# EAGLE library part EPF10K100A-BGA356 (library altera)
EPF10K100 FLEX 10K family
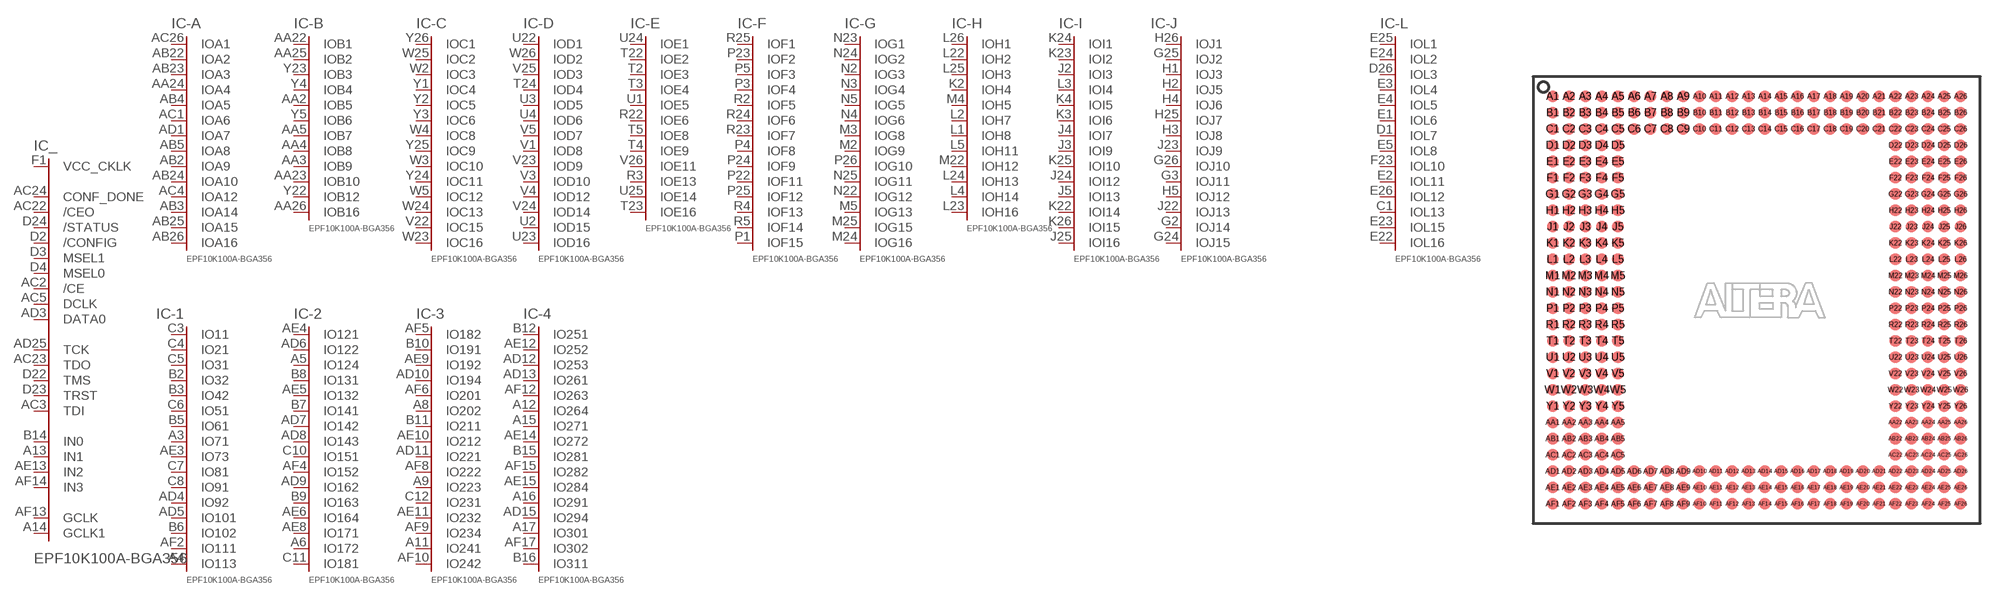
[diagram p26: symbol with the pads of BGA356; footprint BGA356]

Designator prefix IC; gates _=100B356C -A=100A16 -B=100B16 -C=100C16 -D=100D16 -E=100E16 -F=100F15 -G=100G16 -H=100H16 -I=100I16 -J=100J15 -L=100L16 -1=100-113 -2=100-181 -3=100-242 -4=100-311 -5=100-402 -6=100-473 -7=100-524 -K=100K15 G1=GNDINT G2=GNDINT G3=GNDINT G4=GNDINT G5=GNDINT G6=GNDINT G7=GNDINT G8=GNDINT G9=GNDINT G10=GNDINT G11=GNDINT G12=GNDINT G13=GNDINT G14=GNDINT G15=GNDINT G16=GNDINT G17=GNDINT G18=GNDINT G19=GNDINT G20=GNDINT G21=GNDINT G22=GNDINT G23=GNDINT G24=GNDINT G25=GNDINT G26=GNDINT G27=GNDINT G28=GNDINT G29=GNDINT G30=GNDINT G31=GNDINT G32=GNDINT G33=GNDINT V1=VCCINT V2=VCCINT V3=VCCINT V4=VCCINT V5=VCCINT V6=VCCINT V7=VCCINT V8=VCCINT V9=VCCINT V10=VCCINT V11=VCCINT V12=VCCINT V13=VCCINT V14=VCCINT V15=VCCINT VO1=VCCIO VO2=VCCIO VO3=VCCIO VO4=VCCIO VO5=VCCIO VO6=VCCIO VO7=VCCIO VO8=VCCIO VO9=VCCIO VO10=VCCIO VO11=VCCIO VO12=VCCIO VO13=VCCIO VO14=VCCIO VO15=VCCIO VO16=VCCIO VO17=VCCIO VO18=VCCIO VO19=VCCIO

## EPF10K100A-BGA356 (MPN: EPF10K100ABC356-1; OC_FARNELL: unknown; OC_NEWARK: 51R8777)  [BGA356]
A1  V5:VCC  pwr
A2  G12:GND  pwr
A3  -1:IO71
A4  -1:IO113
A5  -2:IO124
A6  -2:IO172
A7  VO7:VCCIO  pwr
A8  -3:IO202
A9  -3:IO223
A10  G13:GND  pwr
A11  -3:IO241
A12  -4:IO264
A13  _:IN1  in
A14  _:GCLK1  in
A15  -4:IO271
A16  -4:IO291
A17  -4:IO301
A18  -5:IO321
A19  -5:IO351
A20  G14:GND  pwr
A21  -5:IO402
A22  -5:IO401
A23  VO8:VCCIO  pwr
A24  -6:IO421
A25  -6:IO451
A26  V6:VCC  pwr
AA1  V1:VCC  pwr
AA2  -B:IOB5
AA3  -B:IOB9
AA4  -B:IOB8
AA5  -B:IOB7
AA22  -B:IOB1
AA23  -B:IOB10
AA24  -A:IOA4
AA25  -B:IOB2
AA26  -B:IOB16
AB1  VO1:VCCIO  pwr
AB2  -A:IOA9
AB3  -A:IOA14
AB4  -A:IOA5
AB5  -A:IOA8
AB22  -A:IOA2
AB23  -A:IOA3
AB24  -A:IOA10
AB25  -A:IOA15
AB26  -A:IOA16
AC1  -A:IOA6
AC2  _:/CE  in
AC3  _:TDI
AC4  -A:IOA12
AC5  _:DCLK  in
AC22  _:/CEO  in
AC23  _:TDO
AC24  _:CONF_DONE  in
AC25  VO2:VCCIO  pwr
AC26  -A:IOA1
AD1  -A:IOA7
AD2  G1:GND  pwr
AD3  _:DATA0  in
AD4  -1:IO92
AD5  -1:IO101
AD6  -2:IO122
AD7  -2:IO142
AD8  -2:IO143
AD9  -2:IO162
AD10  -3:IO194
AD11  -3:IO221
AD12  -4:IO253
AD13  -4:IO261
AD14  G2:GND  pwr
AD15  -4:IO294
AD16  -5:IO364
AD17  -5:IO391
AD18  VO3:VCCIO  pwr
AD19  -6:IO461
AD20  G3:GND  pwr
AD21  -7:IO501
AD22  -7:IO524
AD23  -7:IO512
AD24  -7:IO522
AD25  _:TCK
AD26  V2:VCC  pwr
AE1  G4:GND  pwr
AE2  G5:GND  pwr
AE3  -1:IO73
AE4  -2:IO121
AE5  -2:IO132
AE6  -2:IO164
AE7  G6:GND  pwr
AE8  -2:IO171
AE9  -3:IO192
AE10  -3:IO212
AE11  -3:IO232
AE12  -4:IO252
AE13  _:IN2  in
AE14  -4:IO272
AE15  -4:IO284
AE16  -5:IO323
AE17  -5:IO353
AE18  -5:IO381
AE19  -6:IO423
AE20  -6:IO441
AE21  -6:IO452
AE22  -7:IO482
AE23  -7:IO491
AE24  -7:IO502
AE25  G7:GND  pwr
AE26  G8:GND  pwr
AF1  V3:VCC  pwr
AF2  -1:IO111
AF3  VO4:VCCIO  pwr
AF4  -2:IO152
AF5  -3:IO182
AF6  -3:IO201
AF7  VO5:VCCIO  pwr
AF8  -3:IO222
AF9  -3:IO234
AF10  -3:IO242
AF11  G9:GND  pwr
AF12  -4:IO263
AF13  _:GCLK  in
AF14  _:IN3  in
AF15  -4:IO282
AF16  VO6:VCCIO  pwr
AF17  -4:IO302
AF18  -5:IO333
AF19  G10:GND  pwr
AF20  -5:IO371
AF21  -6:IO404
AF22  -6:IO411
AF23  -6:IO432
AF24  -6:IO471
AF25  G11:GND  pwr
AF26  V4:VCC  pwr
B1  G15:GND  pwr
B2  -1:IO32
B3  -1:IO42
B4  VO9:VCCIO  pwr
B5  -1:IO61
B6  -1:IO102
B7  -2:IO141
B8  -2:IO131
B9  -2:IO163
B10  -3:IO191
B11  -3:IO211
B12  -4:IO251
B13  G16:GND  pwr
B14  _:IN0  in
B15  -4:IO281
B16  -4:IO311
B17  -5:IO331
B18  -5:IO372
B19  -6:IO413
B20  -6:IO414
B21  -6:IO443
B22  G17:GND  pwr
B23  -6:IO473
B24  -7:IO492
B25  G18:GND  pwr
B26  G19:GND  pwr
C1  -L:IOL13
C2  G20:GND  pwr
C3  -1:IO11
C4  -1:IO21
C5  -1:IO31
C6  -1:IO51
C7  -1:IO81
C8  -1:IO91
C9  G21:GND  pwr
C10  -2:IO151
C11  -2:IO181
C12  -3:IO231
C13  G22:GND  pwr
C14  V7:VCC  pwr
C15  VO10:VCCIO  pwr
C16  -5:IO341
C17  -5:IO392
C18  -5:IO361
C19  -6:IO431
C20  -6:IO462
C21  -7:IO481
C22  -7:IO511
C23  -7:IO504
C24  -7:IO521
C25  G23:GND  pwr
C26  V8:VCC  pwr
D1  -L:IOL7
D2  _:/CONFIG  in
D3  _:MSEL1  in
D4  _:MSEL0  in
D5  V9:VCC  pwr
D22  _:TMS
D23  _:TRST
D24  _:/STATUS  in
D25  VO11:VCCIO  pwr
D26  -L:IOL3
E1  -L:IOL6
E2  -L:IOL11
E3  -L:IOL4
E4  -L:IOL5
E5  -L:IOL8
E22  -L:IOL16
E23  -L:IOL15
E24  -L:IOL2
E25  -L:IOL1
E26  -L:IOL12
F1  _:VCC_CKLK  pas
F2  -K:IOK3
F3  -K:IOK8
F4  VO12:VCCIO  pwr
F5  -K:IOK14
F22  -K:IOK2
F23  -L:IOL10
F24  -K:IOK15
F25  -K:IOK1
F26  -K:IOK7
G1  -K:IOK10
G2  -J:IOJ14
G3  -J:IOJ11
G4  -K:IOK4
G5  -K:IOK5
G22  -K:IOK11
G23  -K:IOK6
G24  -J:IOJ15
G25  -J:IOJ2
G26  -J:IOJ10
H1  -J:IOJ3
H2  -J:IOJ5
H3  -J:IOJ8
H4  -J:IOJ6
H5  -J:IOJ12
H22  V10:VCC  pwr
H23  G24:GND  pwr
H24  VO13:VCCIO  pwr
H25  -J:IOJ7
H26  -J:IOJ1
J1  V11:VCC  pwr
J2  -I:IOI3
J3  -I:IOI9
J4  -I:IOI7
J5  -I:IOI13
J22  -J:IOJ13
J23  -J:IOJ9
J24  -I:IOI12
J25  -I:IOI16
J26  G25:GND  pwr
K1  G26:GND  pwr
K2  -H:IOH4
K3  -I:IOI6
K4  -I:IOI5
K5  VO14:VCCIO  pwr
K22  -I:IOI14
K23  -I:IOI2
K24  -I:IOI1
K25  -I:IOI10
K26  -I:IOI15
L1  -H:IOH8
L2  -H:IOH7
L3  -I:IOI4
L4  -H:IOH14
L5  -H:IOH11
L22  -H:IOH2
L23  -H:IOH16
L24  -H:IOH13
L25  -H:IOH3
L26  -H:IOH1
M1  G27:GND  pwr
M2  -G:IOG9
M3  -G:IOG8
M4  -H:IOH5
M5  -G:IOG13
M22  -H:IOH12
M23  VO15:VCCIO  pwr
M24  -G:IOG16
M25  -G:IOG15
M26  V12:VCC  pwr
N1  V13:VCC  pwr
N2  -G:IOG3
N3  -G:IOG4
N4  -G:IOG6
N5  -G:IOG5
N22  -G:IOG12
N23  -G:IOG1
N24  -G:IOG2
N25  -G:IOG11
N26  G28:GND  pwr
P1  -F:IOF15
P2  VO16:VCCIO  pwr
P3  -F:IOF4
P4  -F:IOF8
P5  -F:IOF3
P22  -F:IOF11
P23  -F:IOF2
P24  -F:IOF9
P25  -F:IOF12
P26  -G:IOG10
R1  G29:GND  pwr
R2  -F:IOF5
R3  -E:IOE13
R4  -F:IOF13
R5  -F:IOF14
R22  -E:IOE6
R23  -F:IOF7
R24  -F:IOF6
R25  -F:IOF1
R26  G30:GND  pwr
T1  G31:GND  pwr
T2  -E:IOE3
T3  -E:IOE4
T4  -E:IOE9
T5  -E:IOE8
T22  -E:IOE2
T23  -E:IOE16
T24  -D:IOD4
T25  VO17:VCCIO  pwr
T26  V14:VCC  pwr
U1  -E:IOE5
U2  -D:IOD15
U3  -D:IOD5
U4  -D:IOD6
U5  V15:VCC  pwr
U22  -D:IOD1
U23  -D:IOD16
U24  -E:IOE1
U25  -E:IOE14
U26  G32:GND  pwr
V1  -D:IOD8
V2  VO18:VCCIO  pwr
V3  -D:IOD10
V4  -D:IOD12
V5  -D:IOD7
V22  -C:IOC15
V23  -D:IOD9
V24  -D:IOD14
V25  -D:IOD3
V26  -E:IOE11
W1  G33:GND  pwr
W2  -C:IOC3
W3  -C:IOC10
W4  -C:IOC8
W5  -C:IOC12
W22  VO19:VCCIO  pwr
W23  -C:IOC16
W24  -C:IOC13
W25  -C:IOC2
W26  -D:IOD2
Y1  -C:IOC4
Y2  -C:IOC5
Y3  -C:IOC6
Y4  -B:IOB4
Y5  -B:IOB6
Y22  -B:IOB12
Y23  -B:IOB3
Y24  -C:IOC11
Y25  -C:IOC9
Y26  -C:IOC1

## Footprint BGA356 (pad centres in mm)
Ball Grid Array
smd 0.9 x 0.9: A1 -15.875,15.875; A2 -14.605,15.875; A3 -13.335,15.875; A4 -12.065,15.875; A5 -10.795,15.875; A6 -9.525,15.875; A7 -8.255,15.875; A8 -6.985,15.875; A9 -5.715,15.875; A10 -4.445,15.875; A11 -3.175,15.875; A12 -1.905,15.875; A13 -0.635,15.875; A14 0.635,15.875; A15 1.905,15.875; A16 3.175,15.875; A17 4.445,15.875; A18 5.715,15.875; A19 6.985,15.875; A20 8.255,15.875; A21 9.525,15.875; A22 10.795,15.875; A23 12.065,15.875; A24 13.335,15.875; A25 14.605,15.875; A26 15.875,15.875; AA1 -15.875,-9.525; AA2 -14.605,-9.525; AA3 -13.335,-9.525; AA4 -12.065,-9.525; AA5 -10.795,-9.525; AA22 10.795,-9.525; AA23 12.065,-9.525; AA24 13.335,-9.525; AA25 14.605,-9.525; AA26 15.875,-9.525; AB1 -15.875,-10.795; AB2 -14.605,-10.795; AB3 -13.335,-10.795; AB4 -12.065,-10.795; AB5 -10.795,-10.795; AB22 10.795,-10.795; AB23 12.065,-10.795; AB24 13.335,-10.795; AB25 14.605,-10.795; AB26 15.875,-10.795; AC1 -15.875,-12.065; AC2 -14.605,-12.065; AC3 -13.335,-12.065; AC4 -12.065,-12.065; AC5 -10.795,-12.065; AC22 10.795,-12.065; AC23 12.065,-12.065; AC24 13.335,-12.065; AC25 14.605,-12.065; AC26 15.875,-12.065; AD1 -15.875,-13.335; AD2 -14.605,-13.335; AD3 -13.335,-13.335; AD4 -12.065,-13.335; AD5 -10.795,-13.335; AD6 -9.525,-13.335; AD7 -8.255,-13.335; AD8 -6.985,-13.335; AD9 -5.715,-13.335; AD10 -4.445,-13.335; AD11 -3.175,-13.335; AD12 -1.905,-13.335; AD13 -0.635,-13.335; AD14 0.635,-13.335; AD15 1.905,-13.335; AD16 3.175,-13.335; AD17 4.445,-13.335; AD18 5.715,-13.335; AD19 6.985,-13.335; AD20 8.255,-13.335; AD21 9.525,-13.335; AD22 10.795,-13.335; AD23 12.065,-13.335; AD24 13.335,-13.335; AD25 14.605,-13.335; AD26 15.875,-13.335; AE1 -15.875,-14.605; AE2 -14.605,-14.605; AE3 -13.335,-14.605; AE4 -12.065,-14.605; AE5 -10.795,-14.605; AE6 -9.525,-14.605; AE7 -8.255,-14.605; AE8 -6.985,-14.605; AE9 -5.715,-14.605; AE10 -4.445,-14.605; AE11 -3.175,-14.605; AE12 -1.905,-14.605; AE13 -0.635,-14.605; AE14 0.635,-14.605; AE15 1.905,-14.605; AE16 3.175,-14.605; AE17 4.445,-14.605; AE18 5.715,-14.605; AE19 6.985,-14.605; AE20 8.255,-14.605; AE21 9.525,-14.605; AE22 10.795,-14.605; AE23 12.065,-14.605; AE24 13.335,-14.605; AE25 14.605,-14.605; AE26 15.875,-14.605; AF1 -15.875,-15.875; AF2 -14.605,-15.875; AF3 -13.335,-15.875; AF4 -12.065,-15.875; AF5 -10.795,-15.875; AF6 -9.525,-15.875; AF7 -8.255,-15.875; AF8 -6.985,-15.875; AF9 -5.715,-15.875; AF10 -4.445,-15.875; AF11 -3.175,-15.875; AF12 -1.905,-15.875; AF13 -0.635,-15.875; AF14 0.635,-15.875; AF15 1.905,-15.875; AF16 3.175,-15.875; AF17 4.445,-15.875; AF18 5.715,-15.875; AF19 6.985,-15.875; AF20 8.255,-15.875; AF21 9.525,-15.875; AF22 10.795,-15.875; AF23 12.065,-15.875; AF24 13.335,-15.875; AF25 14.605,-15.875; AF26 15.875,-15.875; B1 -15.875,14.605; B2 -14.605,14.605; B3 -13.335,14.605; B4 -12.065,14.605; B5 -10.795,14.605; B6 -9.525,14.605; B7 -8.255,14.605; B8 -6.985,14.605; B9 -5.715,14.605; B10 -4.445,14.605; B11 -3.175,14.605; B12 -1.905,14.605; B13 -0.635,14.605; B14 0.635,14.605; B15 1.905,14.605; B16 3.175,14.605; B17 4.445,14.605; B18 5.715,14.605; B19 6.985,14.605; B20 8.255,14.605; B21 9.525,14.605; B22 10.795,14.605; B23 12.065,14.605; B24 13.335,14.605; B25 14.605,14.605; B26 15.875,14.605; C1 -15.875,13.335; C2 -14.605,13.335; C3 -13.335,13.335; C4 -12.065,13.335; C5 -10.795,13.335; C6 -9.525,13.335; C7 -8.255,13.335; C8 -6.985,13.335; C9 -5.715,13.335; C10 -4.445,13.335; C11 -3.175,13.335; C12 -1.905,13.335; C13 -0.635,13.335; C14 0.635,13.335; C15 1.905,13.335; C16 3.175,13.335; C17 4.445,13.335; C18 5.715,13.335; C19 6.985,13.335; C20 8.255,13.335; C21 9.525,13.335; C22 10.795,13.335; C23 12.065,13.335; C24 13.335,13.335; C25 14.605,13.335; C26 15.875,13.335; D1 -15.875,12.065; D2 -14.605,12.065; D3 -13.335,12.065; D4 -12.065,12.065; D5 -10.795,12.065; D22 10.795,12.065; D23 12.065,12.065; D24 13.335,12.065; D25 14.605,12.065; D26 15.875,12.065; E1 -15.875,10.795; E2 -14.605,10.795; E3 -13.335,10.795; E4 -12.065,10.795; E5 -10.795,10.795; E22 10.795,10.795; E23 12.065,10.795; E24 13.335,10.795; E25 14.605,10.795; E26 15.875,10.795; F1 -15.875,9.525; F2 -14.605,9.525; F3 -13.335,9.525; F4 -12.065,9.525; F5 -10.795,9.525; F22 10.795,9.525; F23 12.065,9.525; F24 13.335,9.525; F25 14.605,9.525; F26 15.875,9.525; G1 -15.875,8.255; G2 -14.605,8.255; G3 -13.335,8.255; G4 -12.065,8.255; G5 -10.795,8.255; G22 10.795,8.255; G23 12.065,8.255; G24 13.335,8.255; G25 14.605,8.255; G26 15.875,8.255; H1 -15.875,6.985; H2 -14.605,6.985; H3 -13.335,6.985; H4 -12.065,6.985; H5 -10.795,6.985; H22 10.795,6.985; H23 12.065,6.985; H24 13.335,6.985; H25 14.605,6.985; H26 15.875,6.985; J1 -15.875,5.715; J2 -14.605,5.715; J3 -13.335,5.715; J4 -12.065,5.715; J5 -10.795,5.715; J22 10.795,5.715; J23 12.065,5.715; J24 13.335,5.715; J25 14.605,5.715; J26 15.875,5.715; K1 -15.875,4.445; K2 -14.605,4.445; K3 -13.335,4.445; K4 -12.065,4.445; K5 -10.795,4.445; K22 10.795,4.445; K23 12.065,4.445; K24 13.335,4.445; K25 14.605,4.445; K26 15.875,4.445; L1 -15.875,3.175; L2 -14.605,3.175; L3 -13.335,3.175; L4 -12.065,3.175; L5 -10.795,3.175; L22 10.795,3.175; L23 12.065,3.175; L24 13.335,3.175; L25 14.605,3.175; L26 15.875,3.175; M1 -15.875,1.905; M2 -14.605,1.905; M3 -13.335,1.905; M4 -12.065,1.905; M5 -10.795,1.905; M22 10.795,1.905; M23 12.065,1.905; M24 13.335,1.905; M25 14.605,1.905; M26 15.875,1.905; N1 -15.875,0.635; N2 -14.605,0.635; N3 -13.335,0.635; N4 -12.065,0.635; N5 -10.795,0.635; N22 10.795,0.635; N23 12.065,0.635; N24 13.335,0.635; N25 14.605,0.635; N26 15.875,0.635; P1 -15.875,-0.635; P2 -14.605,-0.635; P3 -13.335,-0.635; P4 -12.065,-0.635; P5 -10.795,-0.635; P22 10.795,-0.635; P23 12.065,-0.635; P24 13.335,-0.635; P25 14.605,-0.635; P26 15.875,-0.635; R1 -15.875,-1.905; R2 -14.605,-1.905; R3 -13.335,-1.905; R4 -12.065,-1.905; R5 -10.795,-1.905; R22 10.795,-1.905; R23 12.065,-1.905; R24 13.335,-1.905; R25 14.605,-1.905; R26 15.875,-1.905; T1 -15.875,-3.175; T2 -14.605,-3.175; T3 -13.335,-3.175; T4 -12.065,-3.175; T5 -10.795,-3.175; T22 10.795,-3.175; T23 12.065,-3.175; T24 13.335,-3.175; T25 14.605,-3.175; T26 15.875,-3.175; U1 -15.875,-4.445; U2 -14.605,-4.445; U3 -13.335,-4.445; U4 -12.065,-4.445; U5 -10.795,-4.445; U22 10.795,-4.445; U23 12.065,-4.445; U24 13.335,-4.445; U25 14.605,-4.445; U26 15.875,-4.445; V1 -15.875,-5.715; V2 -14.605,-5.715; V3 -13.335,-5.715; V4 -12.065,-5.715; V5 -10.795,-5.715; V22 10.795,-5.715; V23 12.065,-5.715; V24 13.335,-5.715; V25 14.605,-5.715; V26 15.875,-5.715; W1 -15.875,-6.985; W2 -14.605,-6.985; W3 -13.335,-6.985; W4 -12.065,-6.985; W5 -10.795,-6.985; W22 10.795,-6.985; W23 12.065,-6.985; W24 13.335,-6.985; W25 14.605,-6.985; W26 15.875,-6.985; Y1 -15.875,-8.255; Y2 -14.605,-8.255; Y3 -13.335,-8.255; Y4 -12.065,-8.255; Y5 -10.795,-8.255; Y22 10.795,-8.255; Y23 12.065,-8.255; Y24 13.335,-8.255; Y25 14.605,-8.255; Y26 15.875,-8.255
